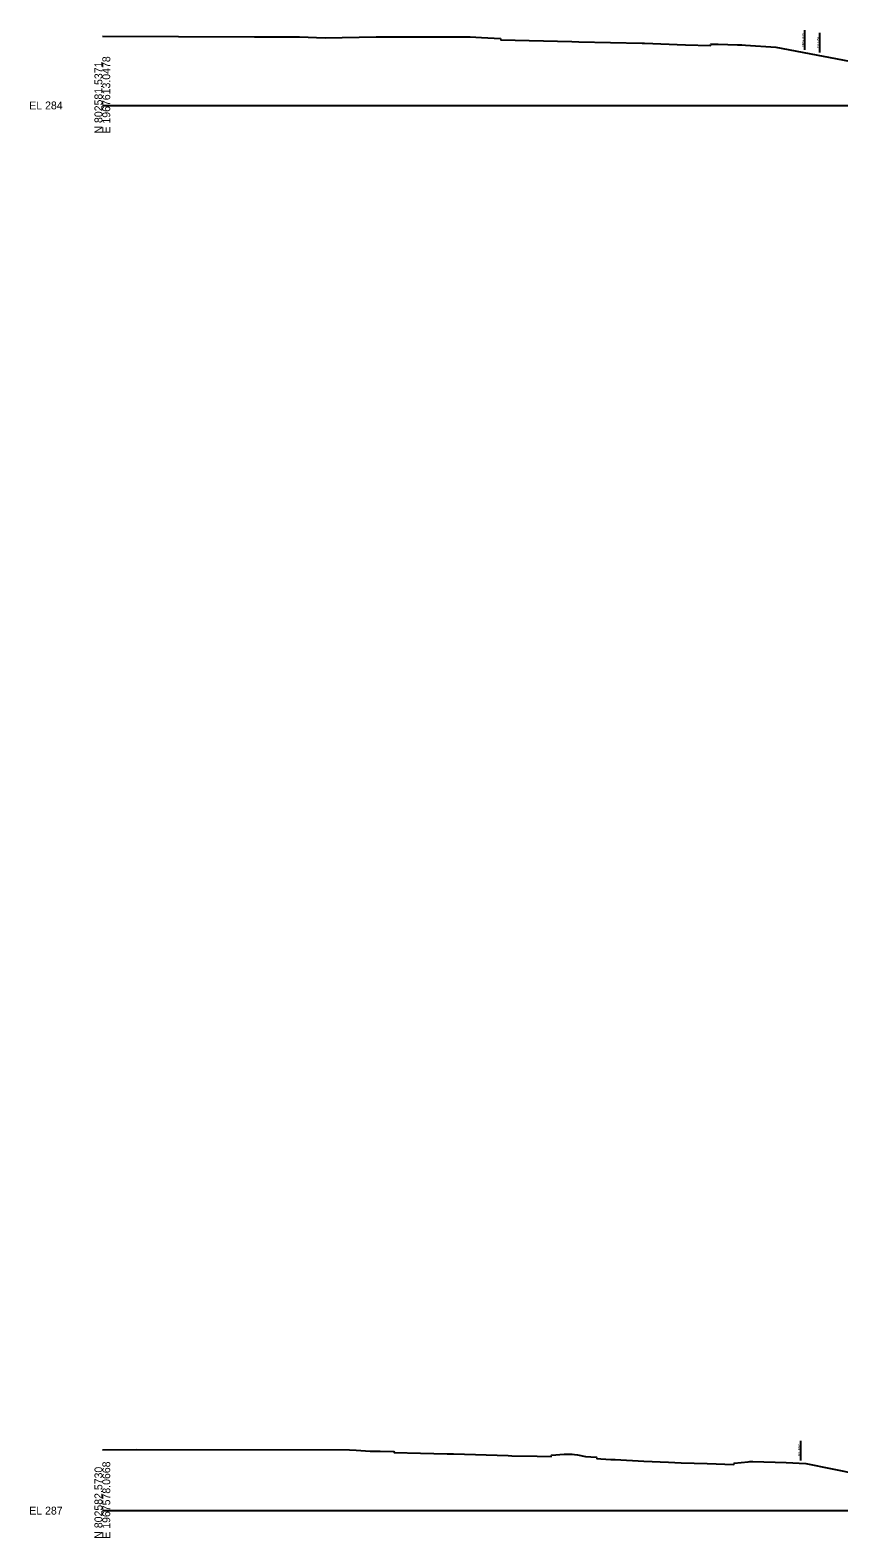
# Model space of a CAD drawing. Extents: x -26 to 1986619, y -10 to 827846.
# Drawn here: x -26 to 262, y 27490 to 28027 of the extents above; entities that cross this region are included whole.
import ezdxf

# ---------------------------------------------------------------- set-up
doc = ezdxf.new("R2010")
doc.units = 0
for name, color, linetype in [('Default', 7, 'Continuous'), ('RD_GPK_XS_Cell', 7, 'Continuous'), ('RD_XS_ExGround', 7, 'Continuous'), ('RD_XS_ExRW', 7, 'Continuous'), ('RD_XS_NewRW', 7, 'Continuous')]:
    doc.layers.add(name, color=color, linetype=linetype)

msp = doc.modelspace()

# ---------------------------------------------------------------- linework, layer by layer
at = {"layer": 'RD_GPK_XS_Cell'}
for p, q in [((0, 28000), (300, 28000)), ((0, 27500), (300, 27500))]:
    msp.add_line(p, q, dxfattribs=at)
at = {"layer": 'RD_XS_ExGround'}
for points in [[(0, 28024.7), (54.13, 28024.41), (70.11, 28024.45), (79.25, 28024.06), (97.49, 28024.39), (103.61, 28024.39), (122.34, 28024.44), (123.89, 28024.44), (130.94, 28024.45), (134.97, 28024.19), (141.69, 28023.77), (141.85, 28023.32), (167.02, 28022.72), (169.52, 28022.66), (192.07, 28022.16), (192.97, 28022.14), (207.47, 28021.62), (216.39, 28021.37), (216.54, 28021.82), (219.19, 28021.8), (226.04, 28021.6), (227.15, 28021.56), (227.52, 28021.55), (228.86, 28021.47), (239.7, 28020.76), (273.34, 28014.33)], [(0, 27521.68), (12.22, 27521.7), (88.01, 27521.68), (90.34, 27521.55), (95.34, 27521.19), (98.92, 27521.17), (103.69, 27521.09), (103.8, 27520.64), (113.24, 27520.43), (122.69, 27520.24), (124.97, 27520.16), (144.45, 27519.57), (145.69, 27519.54), (154.7, 27519.37), (159.71, 27519.31), (159.82, 27519.76), (164.3, 27520.13), (165.28, 27520.14), (165.95, 27520.13), (166.52, 27520.1), (167.19, 27520.07), (167.97, 27520), (169.13, 27519.87), (171.98, 27519.26), (173.83, 27519.16), (175.82, 27519), (175.98, 27518.55), (177.41, 27518.47), (181.01, 27518.24), (182.45, 27518.17), (192.74, 27517.59), (201.52, 27517.27), (206.04, 27517.04), (215.28, 27516.78), (224.78, 27516.4), (224.88, 27516.84), (229.86, 27517.39), (230.38, 27517.45), (230.74, 27517.5), (231.5, 27517.5), (243.4, 27517.13), (250.33, 27516.72), (269.11, 27512.92)]]:
    msp.add_lwpolyline(points, dxfattribs=at)
at = {"layer": 'RD_XS_ExRW'}
for p, q in [((255.3, 28018.78), (255.3, 28025.78)), ((248.62, 27517.83), (248.62, 27524.83))]:
    msp.add_line(p, q, dxfattribs=at)
at = {"layer": 'RD_XS_NewRW'}
msp.add_line((250, 28019.79), (250, 28026.79), dxfattribs=at)

# ---------------------------------------------------------------- texts
at = {"layer": 'Default'}
for p in [(0, 28000), (0, 27500)]:
    msp.add_text('-', height=0.0001, dxfattribs=at).set_placement(p)
at = {"layer": 'RD_GPK_XS_Cell'}
for s, p in [('N 802581.5371', (0, 27990)), ('E 1967613.0478', (2.8, 27990)), ('E 1967578.0668', (2.8, 27490)), ('N 802582.5730', (0, 27490))]:
    msp.add_text(s, height=2.8, rotation=90, dxfattribs=at).set_placement(p)
for s, p in [('EL 284', (-26, 27998.6)), ('EL 287', (-26, 27498.6))]:
    msp.add_text(s, height=2.8, dxfattribs=at).set_placement(p)
at = {"layer": 'RD_XS_ExRW'}
for p in [(255.04, 28020.46), (248.37, 27519.51)]:
    msp.add_text('EX. R/W ', height=0.75, rotation=90, dxfattribs=at).set_placement(p)
at = {"layer": 'RD_XS_NewRW'}
msp.add_text('NEW R/W ', height=0.75, rotation=90, dxfattribs=at).set_placement((249.75, 28020.93))

doc.saveas('drawing.dxf')
